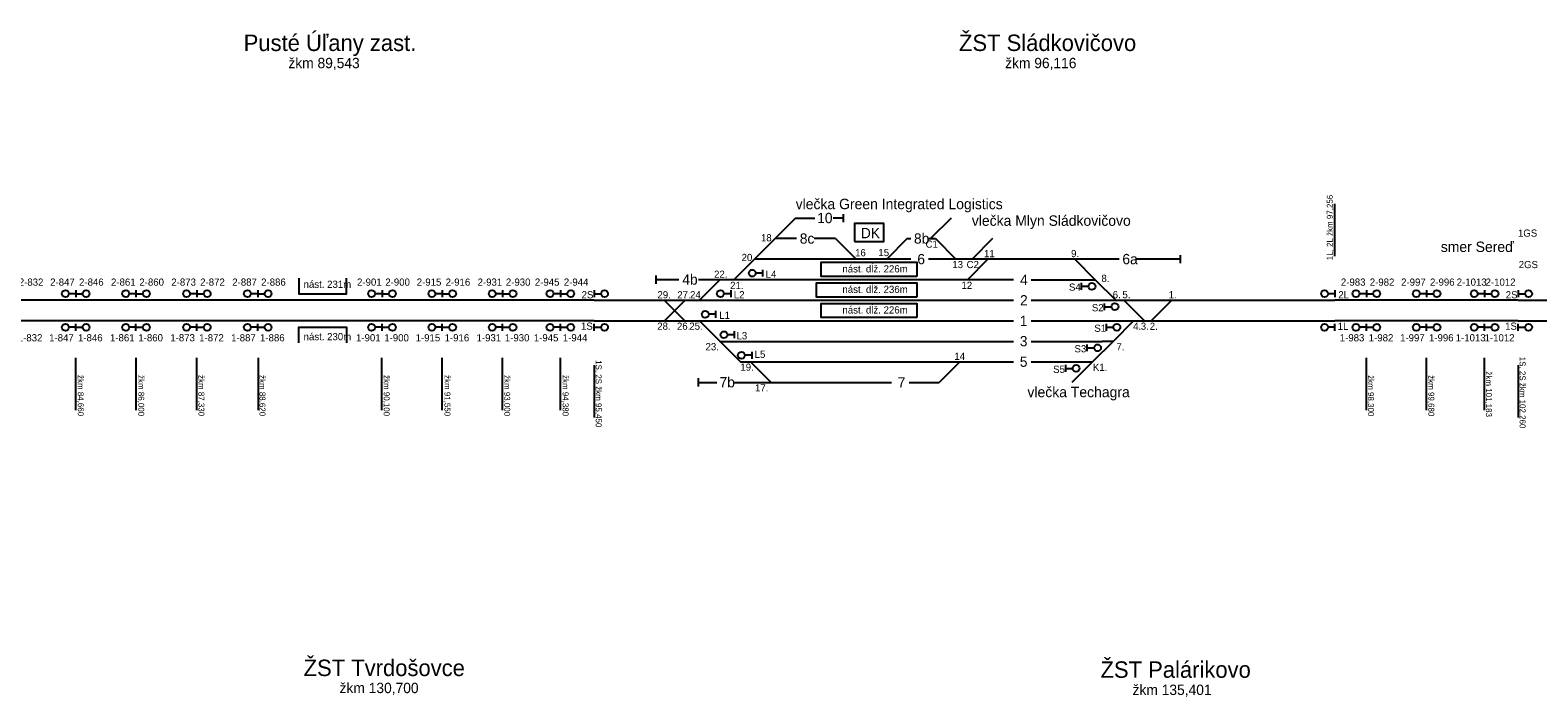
# Model space of a CAD drawing. Extents: x -119 to 851, y -238 to 59.
# Drawn here: x 243.9 to 390.6, y -85.1 to -20.1 of the extents above; entities that cross this region are included whole.
import ezdxf

# ---------------------------------------------------------------- set-up
doc = ezdxf.new("R2010")
doc.units = 0
for name, color, linetype in [('budova', 7, 'Continuous'), ('Level 2', 7, 'Continuous'), ('nastupistia', 7, 'Continuous'), ('netlač', 7, 'Continuous'), ('popisky navestidla', 7, 'Continuous'), ('popisky stanic a zastavok', 7, 'Continuous'), ('PU_navestidla', 7, 'Continuous'), ('PU_oznacenie navestidiel', 7, 'Continuous'), ('PU_stan_kolaje', 7, 'Continuous'), ('PU_vlecky', 7, 'Continuous')]:
    doc.layers.add(name, color=color, linetype=linetype)

msp = doc.modelspace()

# ---------------------------------------------------------------- linework, layer by layer
at = {"layer": 'budova'}
msp.add_lwpolyline([(324.13, -40.72), (327, -40.72), (327, -38.97), (324.13, -38.97)], close=True, dxfattribs=at)
at = {"layer": 'Level 2'}
for p, q in [((323.08, -38.85), (323.08, -38.05)), ((318.5, -42.45), (314.41, -42.45)), ((329.62, -42.45), (318.5, -42.45)), ((339.6, -42.45), (331.35, -42.45)), ((345.57, -42.45), (339.6, -42.45)), ((349.9, -42.45), (345.57, -42.45)), ((355.87, -42.45), (351.63, -42.45)), ((355.87, -42.85), (355.87, -42.05)), ((304.85, -44.85), (304.85, -44.05)), ((307.05, -44.45), (304.85, -44.45)), ((339.6, -44.45), (311.05, -44.45)), ((341.32, -44.45), (347.57, -44.45)), ((298.81, -46.45), (308.43, -46.45)), ((308.43, -46.45), (324.63, -46.45)), ((324.63, -46.45), (339.6, -46.45)), ((341.32, -46.45), (348.22, -46.45)), ((348.22, -46.45), (370.89, -46.45)), ((388.73, -46.45), (405.79, -46.45)), ((298.81, -48.45), (323.43, -48.45)), ((323.43, -48.45), (339.6, -48.45)), ((341.32, -48.45), (349.22, -48.45)), ((349.22, -48.45), (367.52, -48.45)), ((367.52, -48.45), (370.89, -48.45)), ((388.73, -48.45), (420.79, -48.45)), ((311.05, -50.45), (339.6, -50.45)), ((341.32, -50.45), (348.25, -50.45)), ((341.32, -52.45), (347.3, -52.45)), ((308.95, -54.84), (308.95, -54.04)), ((312.46, -54.44), (319.66, -54.44)), ((329.45, -54.44), (332.38, -54.44))]:
    msp.add_line(p, q, dxfattribs=at)
at = {"layer": 'nastupistia'}
for points in [[(330.21, -44.14), (320.89, -44.14), (320.89, -42.75), (330.21, -42.75)], [(330.21, -46.14), (320.44, -46.14), (320.44, -44.75), (330.21, -44.75)], [(330.21, -48.14), (320.89, -48.14), (320.89, -46.75), (330.21, -46.75)]]:
    msp.add_lwpolyline(points, close=True, dxfattribs=at)
for points in [[(270.06, -44.31), (270.06, -45.81), (274.7, -45.81), (274.7, -44.31)], [(270.06, -50.59), (270.06, -49.08), (274.7, -49.08), (274.7, -50.59)]]:
    msp.add_lwpolyline(points, dxfattribs=at)
at = {"layer": 'netlač'}
for p, q in [((318.41, -38.45), (320.28, -38.45)), ((323.08, -38.45), (322.06, -38.45)), ((318.5, -40.45), (316.41, -40.45)), ((322.3, -40.45), (320.22, -40.45)), ((329.28, -40.45), (329.62, -40.45)), ((331.35, -40.45), (332.01, -40.45)), ((311.05, -44.45), (308.98, -44.45)), ((298.81, -46.45), (227.41, -46.45)), ((388.73, -46.45), (370.89, -46.45)), ((298.81, -48.45), (227.41, -48.45)), ((388.73, -48.45), (370.89, -48.45)), ((349.3, -50.45), (348.25, -50.45)), ((313.05, -52.44), (339.6, -52.44)), ((308.95, -54.44), (310.74, -54.44)), ((319.66, -54.44), (327.73, -54.44))]:
    msp.add_line(p, q, dxfattribs=at)
at = {"layer": 'popisky navestidla'}
for p, q in [((370.89, -42.14), (370.89, -37.05)), ((248.33, -52.05), (248.33, -57.14)), ((254.2, -52.05), (254.2, -57.14)), ((260.12, -52.05), (260.12, -57.14)), ((266.11, -52.05), (266.11, -57.14)), ((278.13, -52.05), (278.13, -57.14)), ((284, -52.05), (284, -57.14)), ((289.86, -52.05), (289.86, -57.14)), ((295.5, -52.05), (295.5, -57.14)), ((298.81, -52.76), (298.81, -57.85)), ((373.92, -52.05), (373.92, -57.14)), ((379.78, -52.05), (379.78, -57.14)), ((385.42, -52.05), (385.42, -57.14)), ((388.73, -52.76), (388.73, -57.85))]:
    msp.add_line(p, q, dxfattribs=at)
at = {"layer": 'PU_navestidla'}
for p, q in [((315.2, -43.82), (314.53, -43.82)), ((315.2, -43.48), (315.2, -44.15)), ((248.37, -45.48), (248.37, -46.15)), ((248.37, -45.48), (248.37, -46.15)), ((254.23, -45.48), (254.23, -46.15)), ((254.23, -45.48), (254.23, -46.15)), ((260.16, -45.48), (260.16, -46.15)), ((260.16, -45.48), (260.16, -46.15)), ((266.08, -45.48), (266.08, -46.15)), ((266.08, -45.48), (266.08, -46.15)), ((278.17, -45.48), (278.17, -46.15)), ((278.17, -45.48), (278.17, -46.15)), ((284.03, -45.48), (284.03, -46.15)), ((284.03, -45.48), (284.03, -46.15)), ((289.9, -45.48), (289.9, -46.15)), ((289.9, -45.48), (289.9, -46.15)), ((295.53, -45.48), (295.53, -46.15)), ((295.53, -45.48), (295.53, -46.15)), ((298.81, -45.48), (298.81, -46.15)), ((312.1, -45.48), (312.1, -46.15)), ((346.24, -45.42), (346.24, -44.75)), ((346.24, -45.08), (346.91, -45.08)), ((370.89, -45.48), (370.89, -46.15)), ((373.95, -45.48), (373.95, -46.15)), ((373.95, -45.48), (373.95, -46.15)), ((379.81, -45.48), (379.81, -46.15)), ((379.81, -45.48), (379.81, -46.15)), ((385.45, -45.48), (385.45, -46.15)), ((385.45, -45.48), (385.45, -46.15)), ((388.73, -45.48), (388.73, -46.15)), ((248.37, -45.81), (247.7, -45.81)), ((248.37, -45.81), (249.04, -45.81)), ((254.23, -45.81), (253.56, -45.81)), ((254.23, -45.81), (254.91, -45.81)), ((260.16, -45.81), (259.48, -45.81)), ((260.16, -45.81), (260.83, -45.81)), ((266.08, -45.81), (265.41, -45.81)), ((266.08, -45.81), (266.75, -45.81)), ((278.17, -45.81), (277.5, -45.81)), ((278.17, -45.81), (278.84, -45.81)), ((284.03, -45.81), (283.36, -45.81)), ((284.03, -45.81), (284.7, -45.81)), ((289.9, -45.81), (289.23, -45.81)), ((289.9, -45.81), (290.57, -45.81)), ((295.53, -45.81), (294.86, -45.81)), ((295.53, -45.81), (296.2, -45.81)), ((298.81, -45.81), (299.48, -45.81)), ((312.1, -45.81), (311.43, -45.81)), ((348.47, -47.42), (348.47, -46.75)), ((370.89, -45.81), (370.22, -45.81)), ((373.95, -45.81), (373.28, -45.81)), ((373.95, -45.81), (374.62, -45.81)), ((379.81, -45.81), (379.14, -45.81)), ((379.81, -45.81), (380.49, -45.81)), ((385.45, -45.81), (384.78, -45.81)), ((385.45, -45.81), (386.12, -45.81)), ((388.73, -45.81), (389.4, -45.81)), ((310.63, -47.81), (309.96, -47.81)), ((310.63, -47.48), (310.63, -48.15)), ((348.47, -47.08), (349.14, -47.08)), ((248.37, -49.08), (247.7, -49.08)), ((248.37, -49.42), (248.37, -48.75)), ((248.37, -49.42), (248.37, -48.75)), ((248.37, -49.08), (249.04, -49.08)), ((254.23, -49.08), (253.56, -49.08)), ((254.23, -49.42), (254.23, -48.75)), ((254.23, -49.42), (254.23, -48.75)), ((254.23, -49.08), (254.91, -49.08)), ((260.16, -49.08), (259.48, -49.08)), ((260.16, -49.42), (260.16, -48.75)), ((260.16, -49.42), (260.16, -48.75)), ((260.16, -49.08), (260.83, -49.08)), ((266.08, -49.08), (265.41, -49.08)), ((266.08, -49.42), (266.08, -48.75)), ((266.08, -49.42), (266.08, -48.75)), ((266.08, -49.08), (266.75, -49.08)), ((278.17, -49.08), (277.5, -49.08)), ((278.17, -49.42), (278.17, -48.75)), ((278.17, -49.42), (278.17, -48.75)), ((278.17, -49.08), (278.84, -49.08)), ((284.03, -49.08), (283.36, -49.08)), ((284.03, -49.42), (284.03, -48.75)), ((284.03, -49.42), (284.03, -48.75)), ((284.03, -49.08), (284.7, -49.08)), ((289.9, -49.08), (289.23, -49.08)), ((289.9, -49.42), (289.9, -48.75)), ((289.9, -49.42), (289.9, -48.75)), ((289.9, -49.08), (290.57, -49.08)), ((295.53, -49.08), (294.86, -49.08)), ((295.53, -49.42), (295.53, -48.75)), ((295.53, -49.42), (295.53, -48.75)), ((295.53, -49.08), (296.2, -49.08)), ((298.81, -49.42), (298.81, -48.75)), ((298.81, -49.08), (299.48, -49.08)), ((312.45, -49.81), (311.78, -49.81)), ((312.45, -49.47), (312.45, -50.15)), ((348.66, -49.42), (348.66, -48.75)), ((348.66, -49.08), (349.33, -49.08)), ((370.89, -49.08), (370.22, -49.08)), ((370.89, -49.42), (370.89, -48.75)), ((373.95, -49.08), (373.28, -49.08)), ((373.95, -49.42), (373.95, -48.75)), ((373.95, -49.42), (373.95, -48.75)), ((373.95, -49.08), (374.62, -49.08)), ((379.81, -49.08), (379.14, -49.08)), ((379.81, -49.42), (379.81, -48.75)), ((379.81, -49.42), (379.81, -48.75)), ((379.81, -49.08), (380.49, -49.08)), ((385.45, -49.08), (384.78, -49.08)), ((385.45, -49.42), (385.45, -48.75)), ((385.45, -49.42), (385.45, -48.75)), ((385.45, -49.08), (386.12, -49.08)), ((388.73, -49.42), (388.73, -48.75)), ((388.73, -49.08), (389.4, -49.08)), ((346.79, -51.42), (346.79, -50.75)), ((346.79, -51.08), (347.46, -51.08)), ((314.15, -51.81), (313.48, -51.81)), ((314.15, -51.47), (314.15, -52.14)), ((344.7, -53.42), (344.7, -52.75)), ((344.7, -53.08), (345.37, -53.08))]:
    msp.add_line(p, q, dxfattribs=at)
for centre in [(314.19, -43.81), (247.36, -45.81), (249.38, -45.81), (253.23, -45.81), (255.24, -45.81), (259.15, -45.81), (261.16, -45.81), (265.07, -45.81), (267.09, -45.81), (277.16, -45.81), (279.18, -45.81), (283.02, -45.81), (285.04, -45.81), (288.89, -45.81), (290.91, -45.81), (294.52, -45.81), (296.54, -45.81), (299.82, -45.81), (311.09, -45.81), (347.25, -45.09), (369.88, -45.81), (372.94, -45.81), (374.96, -45.81), (378.81, -45.81), (380.82, -45.81), (384.44, -45.81), (386.46, -45.81), (389.73, -45.81), (349.48, -47.08), (309.62, -47.81), (247.36, -49.08), (249.38, -49.08), (253.23, -49.08), (255.24, -49.08), (259.15, -49.08), (261.16, -49.08), (265.07, -49.08), (267.09, -49.08), (277.16, -49.08), (279.18, -49.08), (283.02, -49.08), (285.04, -49.08), (288.89, -49.08), (290.91, -49.08), (294.52, -49.08), (296.54, -49.08), (299.82, -49.08), (311.44, -49.81), (349.67, -49.08), (369.88, -49.08), (372.94, -49.08), (374.96, -49.08), (378.81, -49.08), (380.82, -49.08), (384.44, -49.08), (386.46, -49.08), (389.73, -49.08), (347.79, -51.08), (313.14, -51.81), (345.71, -53.08)]:
    msp.add_circle(centre, 0.336, dxfattribs=at)
at = {"layer": 'PU_stan_kolaje'}
for points in [[(318.41, -38.45), (316.41, -40.45)], [(333.54, -38.45), (331.54, -40.45)], [(316.41, -40.45), (314.41, -42.45)], [(322.3, -40.45), (324.3, -42.45)], [(329.28, -40.45), (327.28, -42.45)], [(332.01, -40.45), (334.01, -42.45)], [(337.58, -40.45), (335.58, -42.45)], [(314.41, -42.45), (312.41, -44.45)], [(337.13, -42.45), (335.13, -44.45)], [(345.57, -42.45), (347.57, -44.45)], [(311.05, -44.45), (309.05, -46.45)], [(347.57, -44.45), (349.56, -46.45)], [(305.63, -46.45), (307.63, -48.45)], [(307.66, -46.45), (305.66, -48.45)], [(350.35, -46.45), (352.35, -48.45)], [(355.01, -46.45), (353.01, -48.45)], [(309.05, -48.45), (311.05, -50.44)], [(351.3, -48.45), (349.3, -50.45)], [(311.05, -50.44), (313.05, -52.44)], [(349.3, -50.45), (347.3, -52.45)], [(314.03, -52.44), (316.03, -54.44)], [(334.38, -52.45), (332.38, -54.44)], [(347.3, -52.45), (345.3, -54.44)]]:
    msp.add_lwpolyline(points, dxfattribs=at)

# ---------------------------------------------------------------- texts
at = {"layer": 'budova'}
msp.add_text('DK', height=1.004, dxfattribs=at).set_placement((324.76, -40.41))
at = {"layer": 'nastupistia'}
for s, p in [('nást. dĺž. 226m', (322.97, -43.74)), ('nást. 231m', (270.54, -45.24)), ('nást. dĺž. 236m', (322.97, -45.74)), ('nást. dĺž. 226m', (322.97, -47.74)), ('nást. 230m', (270.54, -50.34))]:
    msp.add_text(s, height=0.7, dxfattribs=at).set_placement(p)
at = {"layer": 'popisky navestidla'}
for s, height, rotation, p in [('1L, 2L žkm 97,256', 0.5793, 90, (370.68, -42.55)), ('1S, 2S žkm 95,450', 0.5793, 270, (298.96, -52.28)), ('1S, 2S žkm 102,260', 0.5793, 270, (388.86, -51.95)), ('žkm 84,660', 0.579, 270, (248.57, -53.73)), ('žkm 86,000', 0.579, 270, (254.45, -53.73)), ('žkm 87,330', 0.579, 270, (260.31, -53.73)), ('žkm 88,620', 0.579, 270, (266.25, -53.73)), ('žkm 90,100', 0.579, 270, (278.33, -53.73)), ('žkm 91,550', 0.579, 270, (284.25, -53.73)), ('žkm 93,000', 0.579, 270, (290.06, -53.73)), ('žkm 94,380', 0.579, 270, (295.74, -53.73)), ('žkm 98,300', 0.579, 270, (374.1, -53.75)), ('žkm 99,680', 0.579, 270, (379.98, -53.75)), ('žkm 101,183 ', 0.5793, 270, (385.58, -53.38))]:
    msp.add_text(s, height=height, rotation=rotation, dxfattribs=at).set_placement(p)
at = {"layer": 'popisky stanic a zastavok'}
for s, height, p in [('Pusté Úľany zast.', 1.6, (264.71, -22.18)), ('ŽST Sládkovičovo', 1.6, (334.31, -22.18)), ('žkm 89,543', 1.004, (269.06, -23.85)), ('žkm 96,116', 1.004, (338.8, -23.85)), ('ŽST Tvrdošovce', 1.6, (270.54, -83.04)), ('ŽST Palárikovo', 1.6, (348.08, -83.21)), ('žkm 130,700', 1.0044, (274.04, -84.7)), ('žkm 135,401', 1.0044, (351.2, -84.88))]:
    msp.add_text(s, height=height, dxfattribs=at).set_placement(p)
at = {"layer": 'PU_oznacenie navestidiel'}
for s, p in [('1GS', (388.7, -40.26)), ('18', (315.04, -40.71)), ('C1', (331.06, -41.33)), ('20.', (313.16, -42.63)), ('16', (324.2, -42.17)), ('15', (326.47, -42.15)), ('11', (336.74, -42.26)), ('9.', (345.22, -42.25)), ('22.', (310.48, -44.26)), ('L4', (315.5, -44.26)), ('13', (333.66, -43.32)), ('C2', (335.05, -43.32)), ('8.', (348.17, -44.67)), ('2GS', (388.77, -43.32)), ('2-832', (242.83, -45.03)), ('2-847', (245.88, -45.03)), ('2-846', (248.69, -45.03)), ('2-861', (251.8, -45.03)), ('2-860', (254.56, -45.03)), ('2-873', (257.67, -45.03)), ('2-872', (260.48, -45.03)), ('2-887', (263.6, -45.03)), ('2-886', (266.41, -45.03)), ('2-901', (275.74, -45.03)), ('2-900', (278.49, -45.03)), ('2-915', (281.55, -45.03)), ('2-916', (284.36, -45.03)), ('2-931', (287.47, -45.03)), ('2-930', (290.22, -45.03)), ('2-945', (293.04, -45.03)), ('2-944', (295.86, -45.03)), ('21.', (312.04, -45.35)), ('12', (334.55, -45.34)), ('S4', (345.01, -45.52)), ('2-983', (371.47, -45.03)), ('2-982', (374.28, -45.03)), ('2-997', (377.33, -45.03)), ('2-996', (380.14, -45.03)), ('2-1013', (382.74, -45.03)), ('2-1012', (385.55, -45.03)), ('2S', (297.59, -46.26)), ('29.', (304.97, -46.26)), ('27.', (306.9, -46.27)), ('24.', (308.14, -46.26)), ('L2', (312.4, -46.26)), ('S2', (347.24, -47.52)), ('6.', (349.27, -46.25)), ('5.', (350.21, -46.25)), ('1.', (354.71, -46.26)), ('2L', (371.22, -46.26)), ('2S', (387.51, -46.26)), ('L1', (310.98, -48.26)), ('1-832', (242.73, -50.45)), ('1-847', (245.78, -50.45)), ('1-846', (248.59, -50.45)), ('1-861', (251.7, -50.45)), ('1-860', (254.46, -50.45)), ('1-873', (257.57, -50.45)), ('1-872', (260.38, -50.45)), ('1-887', (263.49, -50.45)), ('1-886', (266.3, -50.45)), ('1-901', (275.64, -50.45)), ('1-900', (278.39, -50.45)), ('1-915', (281.44, -50.45)), ('1-916', (284.26, -50.45)), ('1-931', (287.37, -50.45)), ('1-930', (290.12, -50.45)), ('1-945', (292.94, -50.45)), ('1-944', (295.76, -50.45)), ('1S', (297.53, -49.32)), ('28.', (304.95, -49.32)), ('26.', (306.87, -49.32)), ('25.', (308.07, -49.32)), ('L3', (312.66, -50.25)), ('S1', (347.48, -49.52)), ('4.', (351.26, -49.33)), ('3.', (352, -49.32)), ('2.', (352.87, -49.33)), ('1L', (371.16, -49.33)), ('1-983', (371.36, -50.45)), ('1-982', (374.18, -50.45)), ('1-997', (377.23, -50.45)), ('1-996', (380.04, -50.45)), ('1-1013', (382.64, -50.45)), ('1-1012', (385.45, -50.45)), ('1S', (387.45, -49.32)), ('23.', (309.65, -51.32)), ('S3', (345.55, -51.52)), ('7.', (349.63, -51.33)), ('19.', (313.04, -53.31)), ('L5', (314.43, -52.06)), ('14', (333.86, -52.26)), ('S5', (343.47, -53.52)), ('K1.', (347.34, -53.33)), ('17.', (314.46, -55.33))]:
    msp.add_text(s, height=0.7, dxfattribs=at).set_placement(p)
at = {"layer": 'PU_stan_kolaje'}
for s, height, p in [('10', 1.004, (320.51, -38.94)), ('8c', 1.004, (318.82, -40.94)), ('8b', 1.004, (329.93, -40.94)), ('6', 1, (330.26, -42.94)), ('6a', 1.004, (350.21, -42.94)), ('4b', 1.004, (307.39, -44.93)), ('4', 1, (340.26, -44.95)), ('2', 1, (340.25, -46.95)), ('1', 1, (340.23, -48.95)), ('3', 1, (340.23, -50.93)), ('5', 1, (340.23, -52.93)), ('7b', 1.004, (311.01, -54.93)), ('7', 1, (328.35, -54.95))]:
    msp.add_text(s, height=height, dxfattribs=at).set_placement(p)
at = {"layer": 'PU_vlecky'}
for s, p in [('vlečka Green Integrated Logistics', (318.42, -37.58)), ('vlečka Mlyn Sládkovičovo', (335.56, -39.2)), ('smer Sereď', (381.19, -41.75)), ('vlečka Techagra', (340.97, -55.89))]:
    msp.add_text(s, height=1.015, dxfattribs=at).set_placement(p)

doc.saveas('drawing.dxf')
